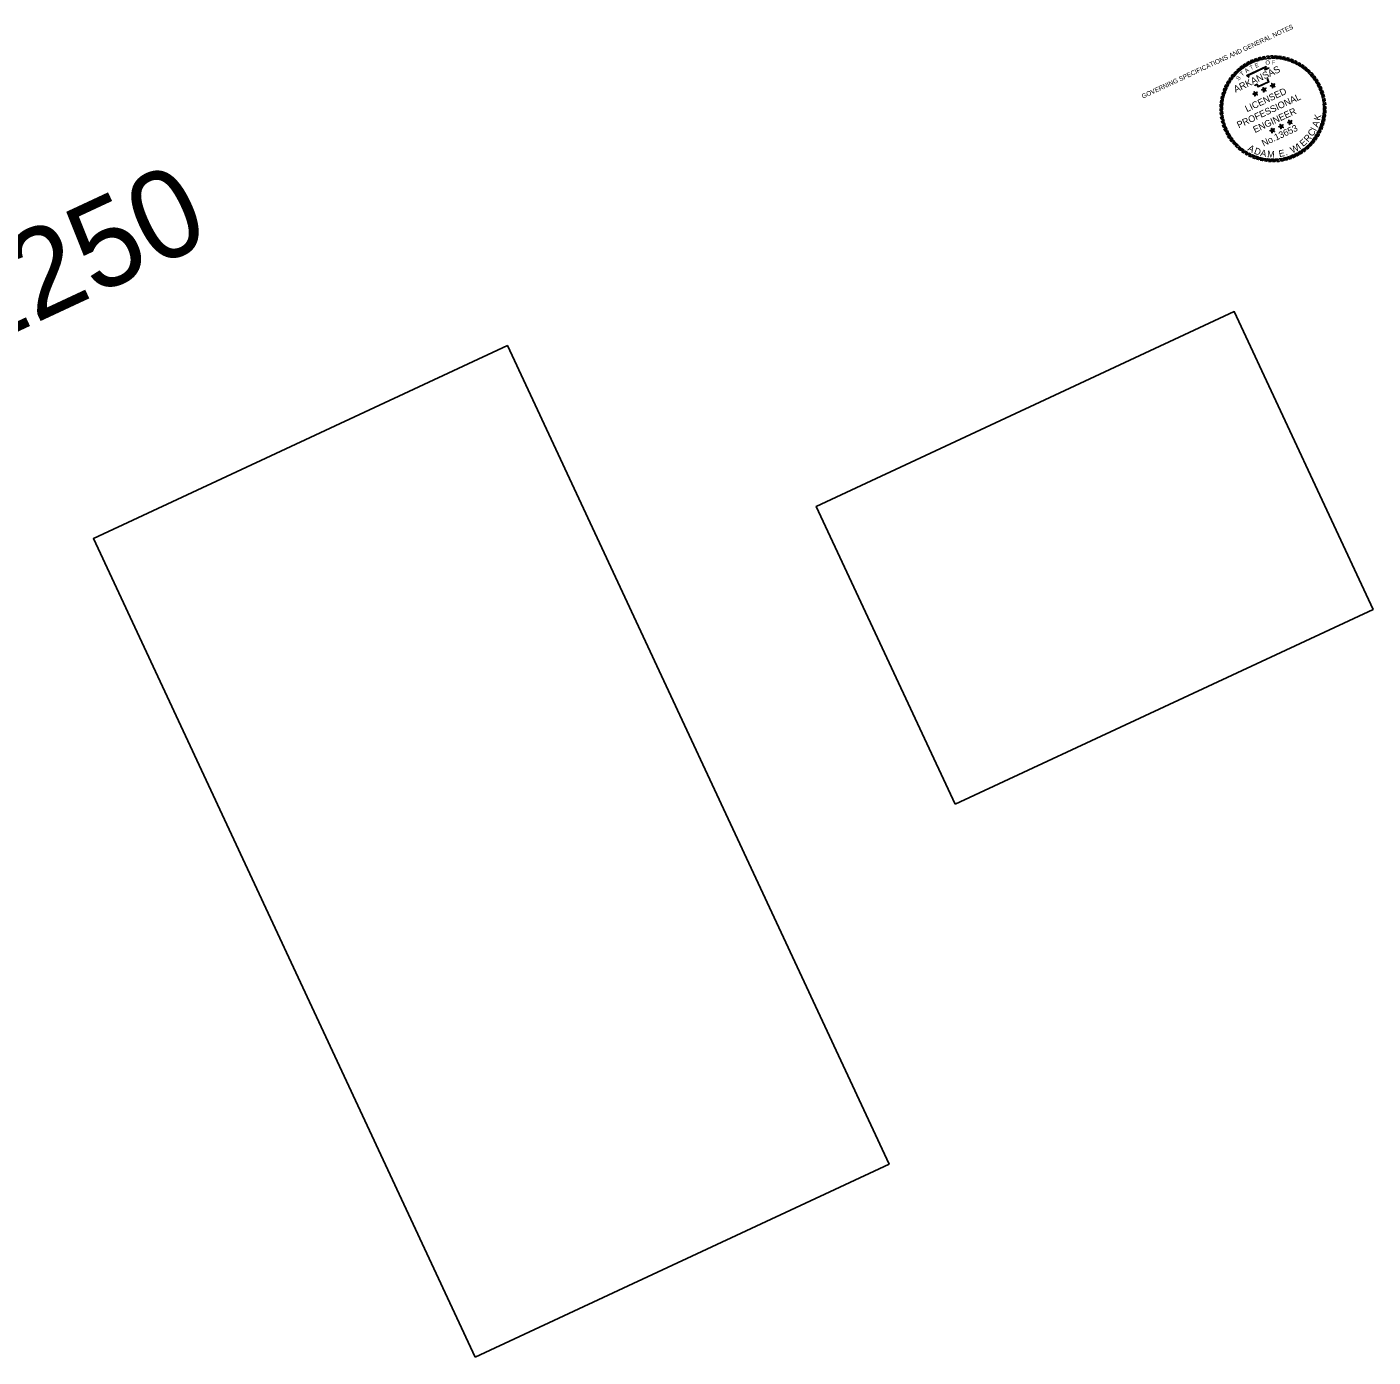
# Model space of a CAD drawing. Extents: x 757022 to 766943, y 1656388 to 1662319.
# Drawn here: x 760075 to 763129, y 1657757 to 1660774 of the extents above; entities that cross this region are included whole.
import ezdxf

# ---------------------------------------------------------------- set-up
doc = ezdxf.new("R2010")
doc.units = 0
for name, color, linetype in [('1', 7, 'Continuous'), ('G-ANNO-STMP-AEW', 7, 'Continuous'), ('G-ANNO-TEXT', 7, 'Continuous')]:
    doc.layers.add(name, color=color, linetype=linetype)

msp = doc.modelspace()

# ---------------------------------------------------------------- linework, layer by layer
at = {"layer": '1'}
for points in [[(762180.6, 1659010.8), (763128.6, 1659452.8), (762813.6, 1660128.4), (761865.6, 1659686.4)], [(761091.9, 1657756.9), (762031, 1658194.9), (761165.3, 1660051.5), (760226.1, 1659613.6)]]:
    msp.add_lwpolyline(points, close=True, dxfattribs=at)
at = {"layer": 'G-ANNO-STMP-AEW'}
for points in [[(762883.5, 1660707.2), (762878.4, 1660706.3), (762872.5, 1660699.3), (762877.9, 1660700.6)], [(762892.9, 1660708.3), (762887.7, 1660707.8), (762881.2, 1660701.3), (762886.8, 1660702.1)], [(762902.3, 1660708.6), (762897.1, 1660708.5), (762890.1, 1660702.5), (762895.7, 1660702.9)], [(762911.7, 1660708.1), (762906.6, 1660708.5), (762899.1, 1660703.1), (762904.7, 1660703)], [(762921.1, 1660707), (762916, 1660707.7), (762908.1, 1660702.9), (762913.7, 1660702.4)], [(762824.2, 1660680.3), (762820.3, 1660676.9), (762818.9, 1660667.8), (762822.8, 1660671.7)], [(762831.6, 1660686.1), (762827.5, 1660683), (762825.3, 1660674), (762829.6, 1660677.7)], [(762839.5, 1660691.3), (762835.1, 1660688.5), (762832.3, 1660679.8), (762836.8, 1660683)], [(762847.7, 1660695.8), (762843.2, 1660693.4), (762839.7, 1660684.9), (762844.4, 1660687.8)], [(762856.3, 1660699.7), (762851.6, 1660697.7), (762847.4, 1660689.5), (762852.4, 1660692)], [(762865.2, 1660702.9), (762860.3, 1660701.3), (762855.5, 1660693.4), (762860.6, 1660695.5)], [(762874.3, 1660705.4), (762869.3, 1660704.1), (762863.9, 1660696.7), (762869.2, 1660698.4)], [(762930.3, 1660705.1), (762925.3, 1660706.2), (762917.1, 1660702), (762922.6, 1660701.1)], [(762939.3, 1660702.5), (762934.4, 1660704), (762925.9, 1660700.5), (762931.3, 1660699.1)], [(762948.2, 1660699.1), (762943.4, 1660701), (762934.6, 1660698.2), (762939.9, 1660696.5)], [(762956.7, 1660695.1), (762952.1, 1660697.4), (762943.1, 1660695.3), (762948.3, 1660693.1)], [(762964.9, 1660690.5), (762960.5, 1660693.1), (762951.4, 1660691.7), (762956.3, 1660689.1)], [(762972.7, 1660685.2), (762968.5, 1660688.2), (762959.3, 1660687.4), (762964, 1660684.5)], [(762980.1, 1660679.3), (762976.1, 1660682.6), (762966.9, 1660682.6), (762971.4, 1660679.3)], [(762986.9, 1660672.9), (762983.2, 1660676.5), (762974.1, 1660677.2), (762978.3, 1660673.6)], [(762799.6, 1660651.9), (762797, 1660647.5), (762798.4, 1660638.4), (762801, 1660643.3)], [(762804.9, 1660659.7), (762801.9, 1660655.5), (762802.7, 1660646.3), (762805.6, 1660651.1)], [(762810.8, 1660667.1), (762807.5, 1660663.1), (762807.5, 1660653.9), (762810.8, 1660658.4)], [(762817.2, 1660674), (762813.6, 1660670.2), (762812.9, 1660661.1), (762816.5, 1660665.3)], [(762901.2, 1660641.1), (762901.6, 1660643.2), (762898.9, 1660646.1), (762899.4, 1660642.2)], [(762993.3, 1660665.9), (762989.9, 1660669.8), (762980.8, 1660671.2), (762984.7, 1660667.3)], [(762999.1, 1660658.5), (762996, 1660662.6), (762987, 1660664.8), (762990.6, 1660660.5)], [(763004.3, 1660650.6), (763001.5, 1660655), (762992.7, 1660657.8), (762996, 1660653.3)], [(763008.8, 1660642.4), (763006.4, 1660646.9), (762997.9, 1660650.4), (763000.8, 1660645.7)], [(762785, 1660617.3), (762783.9, 1660612.3), (762788.1, 1660604.1), (762789, 1660609.6)], [(762787.6, 1660626.4), (762786.1, 1660621.4), (762789.6, 1660612.9), (762791, 1660618.4)], [(762791, 1660635.2), (762789.1, 1660630.4), (762791.9, 1660621.6), (762793.6, 1660626.9)], [(762795, 1660643.7), (762792.7, 1660639.1), (762794.8, 1660630.1), (762797, 1660635.3)], [(762861.5, 1660622.6), (762859.6, 1660623.6), (762856, 1660621.9), (762859.9, 1660621.2)], [(762861.5, 1660622.6), (762861.9, 1660624.7), (762859.1, 1660627.6), (762859.6, 1660623.6)], [(762861.5, 1660622.6), (762859.9, 1660621.2), (762860.4, 1660617.2), (762862.3, 1660620.7)], [(762861.5, 1660622.6), (762863.5, 1660622.8), (762865.5, 1660626.3), (762861.9, 1660624.7)], [(762861.5, 1660622.6), (762862.3, 1660620.7), (762866.3, 1660619.9), (762863.5, 1660622.8)], [(762881.3, 1660631.9), (762879.5, 1660632.9), (762875.9, 1660631.2), (762879.8, 1660630.4)], [(762881.3, 1660631.9), (762881.7, 1660633.9), (762879, 1660636.8), (762879.5, 1660632.9)], [(762881.3, 1660631.9), (762879.8, 1660630.4), (762880.3, 1660626.5), (762882.2, 1660630)], [(762881.3, 1660631.9), (762883.4, 1660632.1), (762885.4, 1660635.6), (762881.7, 1660633.9)], [(762881.3, 1660631.9), (762882.2, 1660630), (762886.1, 1660629.2), (762883.4, 1660632.1)], [(762901.2, 1660641.1), (762899.4, 1660642.2), (762895.8, 1660640.5), (762899.7, 1660639.7)], [(762901.2, 1660641.1), (762899.7, 1660639.7), (762900.2, 1660635.8), (762902.1, 1660639.2)], [(762901.2, 1660641.1), (762903.3, 1660641.4), (762905.2, 1660644.9), (762901.6, 1660643.2)], [(762901.2, 1660641.1), (762902.1, 1660639.2), (762906, 1660638.5), (762903.3, 1660641.4)], [(763012.7, 1660633.8), (763010.7, 1660638.5), (763002.5, 1660642.7), (763005, 1660637.7)], [(763015.9, 1660624.9), (763014.2, 1660629.8), (763006.4, 1660634.6), (763008.5, 1660629.5)], [(763018.4, 1660615.8), (763017.1, 1660620.8), (763009.7, 1660626.2), (763011.4, 1660620.9)], [(763020.2, 1660606.6), (763019.3, 1660611.7), (763012.3, 1660617.6), (763013.6, 1660612.2)], [(762781.5, 1660589.3), (762781.6, 1660584.2), (762787.6, 1660577.2), (762787.2, 1660582.7)], [(762782, 1660598.7), (762781.6, 1660593.6), (762787, 1660586.1), (762787.1, 1660591.7)], [(762783.1, 1660608.1), (762782.4, 1660603), (762787.2, 1660595.1), (762787.7, 1660600.7)], [(763021.2, 1660597.2), (763020.8, 1660602.4), (763014.3, 1660608.9), (763015.1, 1660603.3)], [(763021.5, 1660587.8), (763021.5, 1660593), (763015.5, 1660600), (763015.9, 1660594.4)], [(763021.1, 1660578.4), (763021.4, 1660583.5), (763016, 1660591), (763016, 1660585.4)], [(762781.8, 1660579.9), (762782.3, 1660574.8), (762788.8, 1660568.3), (762788, 1660573.8)], [(762782.9, 1660570.5), (762783.8, 1660565.5), (762790.8, 1660559.5), (762789.5, 1660564.9)], [(762784.7, 1660561.3), (762786, 1660556.3), (762793.4, 1660550.9), (762791.7, 1660556.2)], [(762940.1, 1660557.9), (762938.2, 1660558.9), (762934.6, 1660557.2), (762938.5, 1660556.4)], [(762940.1, 1660557.9), (762940.5, 1660559.9), (762937.8, 1660562.8), (762938.2, 1660558.9)], [(762940.1, 1660557.9), (762938.5, 1660556.4), (762939, 1660552.5), (762941, 1660556)], [(762940.1, 1660557.9), (762942.1, 1660558.1), (762944.1, 1660561.6), (762940.5, 1660559.9)], [(762940.1, 1660557.9), (762941, 1660556), (762944.9, 1660555.2), (762942.1, 1660558.1)], [(763012.1, 1660541.9), (763014, 1660546.7), (763011.2, 1660555.5), (763009.4, 1660550.2)], [(763015.4, 1660550.8), (763017, 1660555.7), (763013.4, 1660564.2), (763012.1, 1660558.8)], [(763018.1, 1660559.8), (763019.2, 1660564.8), (763015, 1660573), (763014.1, 1660567.5)], [(763020, 1660569), (763020.7, 1660574.1), (763015.9, 1660582), (763015.4, 1660576.4)], [(762787.2, 1660552.2), (762788.8, 1660547.3), (762796.7, 1660542.5), (762794.6, 1660547.7)], [(762790.4, 1660543.3), (762792.4, 1660538.6), (762800.6, 1660534.4), (762798.1, 1660539.4)], [(762794.3, 1660534.8), (762796.7, 1660530.2), (762805.2, 1660526.7), (762802.3, 1660531.4)], [(762798.8, 1660526.5), (762801.6, 1660522.1), (762810.3, 1660519.3), (762807.1, 1660523.8)], [(762900.3, 1660539.3), (762898.5, 1660540.3), (762894.8, 1660538.6), (762898.8, 1660537.9)], [(762900.3, 1660539.3), (762900.7, 1660541.4), (762898, 1660544.3), (762898.5, 1660540.3)], [(762900.3, 1660539.3), (762898.8, 1660537.9), (762899.2, 1660533.9), (762901.2, 1660537.4)], [(762900.3, 1660539.3), (762902.4, 1660539.6), (762904.3, 1660543.1), (762900.7, 1660541.4)], [(762900.3, 1660539.3), (762901.2, 1660537.4), (762905.1, 1660536.7), (762902.4, 1660539.6)], [(762920.2, 1660548.6), (762918.3, 1660549.6), (762914.7, 1660547.9), (762918.6, 1660547.2)], [(762920.2, 1660548.6), (762920.6, 1660550.6), (762917.9, 1660553.6), (762918.3, 1660549.6)], [(762920.2, 1660548.6), (762918.6, 1660547.2), (762919.1, 1660543.2), (762921.1, 1660546.7)], [(762920.2, 1660548.6), (762922.3, 1660548.8), (762924.2, 1660552.3), (762920.6, 1660550.6)], [(762920.2, 1660548.6), (762921.1, 1660546.7), (762925, 1660545.9), (762922.3, 1660548.8)], [(762998.2, 1660517.4), (763001.2, 1660521.6), (763000.4, 1660530.8), (762997.5, 1660526.1)], [(763003.5, 1660525.2), (763006.1, 1660529.6), (763004.7, 1660538.7), (763002.1, 1660533.8)], [(763008.1, 1660533.4), (763010.4, 1660538), (763008.2, 1660547), (763006.1, 1660541.8)], [(762804, 1660518.6), (762807.1, 1660514.5), (762816.1, 1660512.4), (762812.4, 1660516.6)], [(762809.8, 1660511.2), (762813.2, 1660507.3), (762822.3, 1660505.9), (762818.4, 1660509.8)], [(762816.1, 1660504.2), (762819.9, 1660500.6), (762829, 1660499.9), (762824.8, 1660503.6)], [(762823, 1660497.8), (762827, 1660494.5), (762836.2, 1660494.5), (762831.7, 1660497.8)], [(762963.6, 1660485.8), (762968, 1660488.6), (762970.8, 1660497.4), (762966.3, 1660494.1)], [(762971.5, 1660491), (762975.6, 1660494.1), (762977.7, 1660503.1), (762973.5, 1660499.5)], [(762978.9, 1660496.8), (762982.8, 1660500.2), (762984.2, 1660509.3), (762980.3, 1660505.4)], [(762985.9, 1660503.2), (762989.5, 1660506.9), (762990.2, 1660516), (762986.5, 1660511.8)], [(762992.3, 1660510), (762995.6, 1660514), (762995.6, 1660523.2), (762992.3, 1660518.7)], [(762830.4, 1660491.9), (762834.6, 1660488.9), (762843.8, 1660489.7), (762839, 1660492.6)], [(762838.2, 1660486.6), (762842.6, 1660484), (762851.7, 1660485.4), (762846.8, 1660488)], [(762846.4, 1660482), (762851, 1660479.7), (762860, 1660481.9), (762854.8, 1660484)], [(762854.9, 1660478), (762859.7, 1660476.1), (762868.5, 1660478.9), (762863.2, 1660480.7)], [(762863.7, 1660474.7), (762868.7, 1660473.1), (762877.2, 1660476.7), (762871.7, 1660478)], [(762872.8, 1660472), (762877.8, 1660470.9), (762886, 1660475.1), (762880.5, 1660476)], [(762882, 1660470.1), (762887.1, 1660469.4), (762895, 1660474.2), (762889.4, 1660474.7)], [(762891.4, 1660469), (762896.5, 1660468.7), (762904, 1660474.1), (762898.4, 1660474.1)], [(762900.8, 1660468.6), (762905.9, 1660468.6), (762912.9, 1660474.6), (762907.4, 1660474.2)], [(762910.2, 1660468.9), (762915.3, 1660469.3), (762921.8, 1660475.9), (762916.3, 1660475)], [(762919.6, 1660469.9), (762924.7, 1660470.8), (762930.6, 1660477.8), (762925.2, 1660476.5)], [(762928.8, 1660471.7), (762933.8, 1660473), (762939.2, 1660480.4), (762933.9, 1660478.7)], [(762937.9, 1660474.2), (762942.8, 1660475.9), (762947.6, 1660483.7), (762942.4, 1660481.6)], [(762946.8, 1660477.4), (762951.5, 1660479.4), (762955.7, 1660487.6), (762950.7, 1660485.1)], [(762955.3, 1660481.3), (762959.9, 1660483.7), (762963.4, 1660492.2), (762958.7, 1660489.3)]]:
    msp.add_lwpolyline(points, close=True, dxfattribs=at)
for points in [[(762847.3, 1660659.4), (762842.2, 1660663.7), (762886.1, 1660684.2), (762884.6, 1660677.8), (762887.5, 1660679.3), (762890, 1660680.5), (762892.6, 1660681.4)], [(762847.8, 1660660), (762843.6, 1660663.5), (762885, 1660682.8), (762883.4, 1660676.5), (762887.8, 1660678.6), (762890.3, 1660679.8), (762892.8, 1660680.6)], [(762890.3, 1660657), (762889.8, 1660656.1), (762890, 1660655.1), (762890.8, 1660652.7), (762892.2, 1660649.6), (762867.8, 1660638.2), (762865.8, 1660642.3), (762865.4, 1660643.2), (762864.3, 1660643.1), (762860.8, 1660641.4), (762859.7, 1660642.1)], [(762889.6, 1660657.4), (762889, 1660656.2), (762889.3, 1660654.9), (762890.1, 1660652.4), (762891.2, 1660650), (762868.1, 1660639.2), (762866.5, 1660642.6), (762865.9, 1660644.1), (762864.1, 1660643.8), (762860.9, 1660642.3), (762860.1, 1660642.7)]]:
    msp.add_lwpolyline(points, dxfattribs=at)

# ---------------------------------------------------------------- texts
at = {"layer": '1'}
for s, height, p in [('GOVERNING SPECIFICATIONS AND GENERAL NOTES', 10.552, (762606.8, 1660611.4)), ('PASTE SCALE = 1250', 200, (758026.3, 1659137))]:
    msp.add_text(s, height=height, rotation=25, dxfattribs=at).set_placement(p)
at = {"layer": 'G-ANNO-TEXT'}
for s, height, rotation, p in [('ARKANSAS', 15.58, 25, (762816.7, 1660624.7)), ('A', 9.55, 33.6788, (762841, 1660669.3)), ('T', 9.55, 26.4789, (762851.4, 1660676.2)), ('E', 9.55, 21.672, (762862.6, 1660681.1)), ('O', 9.55, 6.2218, (762885, 1660688)), ('F', 9.55, 0.3628, (762898.8, 1660688.9)), ('S', 9.55, 44.7726, (762823.1, 1660651.6)), ('T', 9.55, 41.9015, (762831.8, 1660661.7)), ('PROFESSIONAL', 15.087, 25, (762824, 1660544.1)), ('LICENSED', 15.09, 25, (762842.6, 1660580.6)), ('ENGINEER', 15.09, 25, (762860.7, 1660533.4)), ('A', 15.1, 70.185, (763003.4, 1660545.5)), ('K', 15.1, 78.8471, (763008.7, 1660561)), ('No.13653', 15.03, 25, (762880.2, 1660502.8)), ('R', 15.1, 49.1616, (762981.2, 1660511.9)), ('C', 15.1, 57.1396, (762991.6, 1660524.5)), ('I', 15.1, 63.4057, (762999.1, 1660536.8)), ('A', 15.1, 330.982, (762842.8, 1660494.9)), ('D', 15.1, 339.3022, (762857.3, 1660487.2)), ('A', 15.1, 347.6223, (762872.1, 1660482)), ('M', 15.1, 356.7969, (762888.1, 1660478.7)), ('E', 15.1, 10.2782, (762916, 1660479)), ('W', 15.1, 27.1127, (762945.4, 1660487)), ('I', 15.1, 34.5753, (762962, 1660496.1)), ('E', 15.1, 41.0125, (762970, 1660501.8)), ('.', 15.1, 15.8583, (762930.8, 1660482.1))]:
    msp.add_text(s, height=height, rotation=rotation, dxfattribs=at).set_placement(p)

doc.saveas('drawing.dxf')
